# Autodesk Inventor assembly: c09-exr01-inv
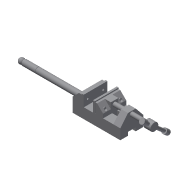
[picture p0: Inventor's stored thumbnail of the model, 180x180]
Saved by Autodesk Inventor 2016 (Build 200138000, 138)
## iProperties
Created: 2011-07
Part Number: c09-exr01-inv
Document SubType Name: Assembly
Designer: CadCim
Author: CadCim
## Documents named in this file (9)
- D:\KAVITA\Autodesk Inventor_ 2016 Project_Kavita\Inventor_Part Files\Inventor_2016_tut\c10_Inv_tut_2015\c10_tut02_inv\Drill Press Vice\c09-exr01-inv.iam
- D:\KAVITA\Autodesk Inventor_ 2016 Project_Kavita\Inventor_Part Files\Inventor_2016_tut\c10_Inv_tut_2015\c10_tut02_inv\Drill Press Vice\Base.ipt
- D:\KAVITA\Autodesk Inventor_ 2016 Project_Kavita\Inventor_Part Files\Inventor_2016_tut\c10_Inv_tut_2015\c10_tut02_inv\Drill Press Vice\Jaw Face.ipt
- D:\KAVITA\Autodesk Inventor_ 2016 Project_Kavita\Inventor_Part Files\Inventor_2016_tut\c10_Inv_tut_2015\c10_tut02_inv\Drill Press Vice\Movable Jaw.ipt
- D:\KAVITA\Autodesk Inventor_ 2016 Project_Kavita\Inventor_Part Files\Inventor_2016_tut\c10_Inv_tut_2015\c10_tut02_inv\Drill Press Vice\Safety Handle.ipt
- D:\KAVITA\Autodesk Inventor_ 2016 Project_Kavita\Inventor_Part Files\Inventor_2016_tut\c10_Inv_tut_2015\c10_tut02_inv\Drill Press Vice\Clamp Screw.ipt
- D:\KAVITA\Autodesk Inventor_ 2016 Project_Kavita\Inventor_Part Files\Inventor_2016_tut\c10_Inv_tut_2015\c10_tut02_inv\Drill Press Vice\Clamp Screw Handle.ipt
- D:\KAVITA\Autodesk Inventor_ 2016 Project_Kavita\Inventor_Part Files\Inventor_2016_tut\c10_Inv_tut_2015\c10_tut02_inv\Drill Press Vice\Handle Stop.ipt
- D:\KAVITA\Autodesk Inventor_ 2016 Project_Kavita\Inventor_Part Files\Inventor_2016_tut\c10_Inv_tut_2015\c10_tut02_inv\Drill Press Vice\Cap Screw.ipt
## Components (11 placed, 8 different names)
1. Base:1 — Insert:1, Insert:2, Insert:3
2. Jaw Face:1 — Insert:1, Insert:2, Mate:1, Mate:2, Mate:5, Mate:7
3. Movable Jaw:1 — Mate:1, Mate:2, Mate:3, Insert:4, Insert:5, Insert:6, Insert:9, Insert:10
4. Safety Handle:1 — Insert:3
5. Clamp Screw:1 — Mate:3, Insert:4, Mate:4, Mate:6
6. Clamp Screw Handle:1 — Mate:4, Insert:7, Insert:8
7. Jaw Face:2 — Insert:5, Insert:6, Mate:5, Mate:7
8. Handle Stop:1 — Insert:7, Mate:6
9. Handle Stop:2 — Insert:8
10. Cap Screw:2 — Insert:9
11. Cap Screw:3 — Insert:10
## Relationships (17: Insert 10, Mate 7)
- Insert:1: Base:1 ↔ Jaw Face:1
- Insert:2: Base:1 ↔ Jaw Face:1
- Mate:1: Jaw Face:1 ↔ Movable Jaw:1
- Mate:2: Jaw Face:1 ↔ Movable Jaw:1
- Insert:3: Base:1 ↔ Safety Handle:1
- Mate:3: Movable Jaw:1 ↔ Clamp Screw:1
- Insert:4: Movable Jaw:1 ↔ Clamp Screw:1
- Mate:4: Clamp Screw:1 ↔ Clamp Screw Handle:1
- Insert:5: Movable Jaw:1 ↔ Jaw Face:2
- Insert:6: Movable Jaw:1 ↔ Jaw Face:2
- Mate:5: Jaw Face:1 ↔ Jaw Face:2
- Insert:7: Clamp Screw Handle:1 ↔ Handle Stop:1
- Insert:8: Clamp Screw Handle:1 ↔ Handle Stop:2
- Mate:6: Clamp Screw:1 ↔ Handle Stop:1
- Mate:7: Jaw Face:1 ↔ Jaw Face:2
- Insert:9: Movable Jaw:1 ↔ Cap Screw:2
- Insert:10: Movable Jaw:1 ↔ Cap Screw:3
